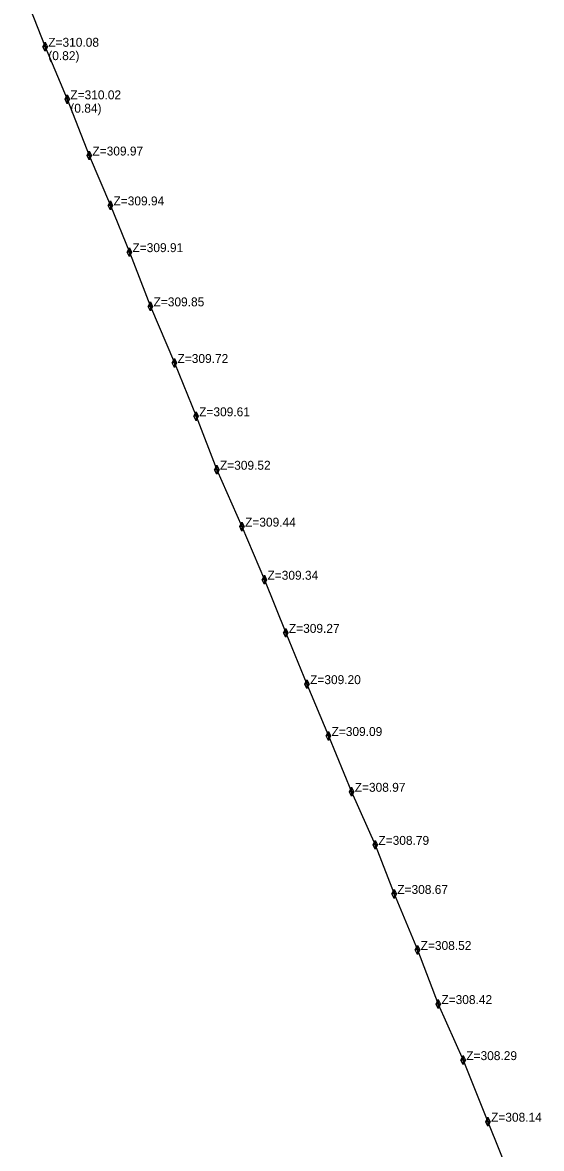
# Model space of a CAD drawing. Extents: x 799271 to 799523, y 67737 to 68184.
# Drawn here: x 799364.5 to 799387.8, y 67960.9 to 68011.4 of the extents above; entities that cross this region are included whole.
import ezdxf

# ---------------------------------------------------------------- set-up
doc = ezdxf.new("R2010")
doc.units = 0
doc.layers.add('PGOC_HTA_CONSTRUIT', color=7, linetype='Continuous')
doc.layers.add('PGOC_PTRL', color=7, linetype='Continuous')

msp = doc.modelspace()

# ---------------------------------------------------------------- linework, layer by layer
at = {"layer": 'PGOC_HTA_CONSTRUIT'}
msp.add_lwpolyline([(799364.509, 68012.954), (799365.523, 68010.352), (799366.514, 68007.996), (799367.503, 68005.475), (799368.447, 68003.238), (799369.299, 68001.141), (799370.244, 67998.71), (799371.319, 67996.17), (799372.29, 67993.779), (799373.221, 67991.381), (799374.349, 67988.83), (799375.353, 67986.448), (799376.313, 67984.066), (799377.264, 67981.766), (799378.226, 67979.44), (799379.265, 67976.938), (799380.327, 67974.558), (799381.173, 67972.357), (799382.222, 67969.845), (799383.151, 67967.417), (799384.268, 67964.903), (799385.38, 67962.141), (799386.421, 67959.533)], dxfattribs=at)
at = {"layer": 'PGOC_PTRL'}
for points in [[(799365.423, 68010.352), (799365.523, 68010.552), (799365.623, 68010.352), (799365.523, 68010.152), (799365.423, 68010.352)], [(799365.623, 68010.352), (799365.523, 68010.352), (799365.423, 68010.352)], [(799365.523, 68010.552), (799365.523, 68010.152)], [(799366.414, 68007.996), (799366.514, 68008.196), (799366.614, 68007.996), (799366.514, 68007.796), (799366.414, 68007.996)], [(799366.614, 68007.996), (799366.514, 68007.996), (799366.414, 68007.996)], [(799366.514, 68008.196), (799366.514, 68007.796)], [(799367.403, 68005.475), (799367.503, 68005.675), (799367.603, 68005.475), (799367.503, 68005.275), (799367.403, 68005.475)], [(799367.603, 68005.475), (799367.503, 68005.475), (799367.403, 68005.475)], [(799367.503, 68005.675), (799367.503, 68005.275)], [(799368.347, 68003.238), (799368.447, 68003.438), (799368.547, 68003.238), (799368.447, 68003.038), (799368.347, 68003.238)], [(799368.447, 68003.438), (799368.447, 68003.038)], [(799368.547, 68003.238), (799368.447, 68003.238), (799368.347, 68003.238)], [(799369.199, 68001.141), (799369.299, 68001.341), (799369.399, 68001.141), (799369.299, 68000.941), (799369.199, 68001.141)], [(799369.299, 68001.341), (799369.299, 68000.941)], [(799369.399, 68001.141), (799369.299, 68001.141), (799369.199, 68001.141)], [(799370.144, 67998.71), (799370.244, 67998.91), (799370.344, 67998.71), (799370.244, 67998.51), (799370.144, 67998.71)], [(799370.244, 67998.91), (799370.244, 67998.51)], [(799370.344, 67998.71), (799370.244, 67998.71), (799370.144, 67998.71)], [(799371.219, 67996.17), (799371.319, 67996.37), (799371.419, 67996.17), (799371.319, 67995.97), (799371.219, 67996.17)], [(799371.319, 67996.37), (799371.319, 67995.97)], [(799371.419, 67996.17), (799371.319, 67996.17), (799371.219, 67996.17)], [(799372.19, 67993.779), (799372.29, 67993.979), (799372.39, 67993.779), (799372.29, 67993.579), (799372.19, 67993.779)], [(799372.39, 67993.779), (799372.29, 67993.779), (799372.19, 67993.779)], [(799372.29, 67993.979), (799372.29, 67993.579)], [(799373.121, 67991.381), (799373.221, 67991.581), (799373.321, 67991.381), (799373.221, 67991.181), (799373.121, 67991.381)], [(799373.321, 67991.381), (799373.221, 67991.381), (799373.121, 67991.381)], [(799373.221, 67991.581), (799373.221, 67991.181)], [(799374.249, 67988.83), (799374.349, 67989.03), (799374.449, 67988.83), (799374.349, 67988.63), (799374.249, 67988.83)], [(799374.449, 67988.83), (799374.349, 67988.83), (799374.249, 67988.83)], [(799374.349, 67989.03), (799374.349, 67988.63)], [(799375.253, 67986.448), (799375.353, 67986.648), (799375.453, 67986.448), (799375.353, 67986.248), (799375.253, 67986.448)], [(799375.353, 67986.648), (799375.353, 67986.248)], [(799375.453, 67986.448), (799375.353, 67986.448), (799375.253, 67986.448)], [(799376.213, 67984.066), (799376.313, 67984.266), (799376.413, 67984.066), (799376.313, 67983.866), (799376.213, 67984.066)], [(799376.313, 67984.266), (799376.313, 67983.866)], [(799376.413, 67984.066), (799376.313, 67984.066), (799376.213, 67984.066)], [(799377.164, 67981.766), (799377.264, 67981.966), (799377.364, 67981.766), (799377.264, 67981.566), (799377.164, 67981.766)], [(799377.364, 67981.766), (799377.264, 67981.766), (799377.164, 67981.766)], [(799377.264, 67981.966), (799377.264, 67981.566)], [(799378.126, 67979.44), (799378.226, 67979.64), (799378.326, 67979.44), (799378.226, 67979.24), (799378.126, 67979.44)], [(799378.226, 67979.64), (799378.226, 67979.24)], [(799378.326, 67979.44), (799378.226, 67979.44), (799378.126, 67979.44)], [(799379.165, 67976.938), (799379.265, 67977.138), (799379.365, 67976.938), (799379.265, 67976.738), (799379.165, 67976.938)], [(799379.265, 67977.138), (799379.265, 67976.738)], [(799379.365, 67976.938), (799379.265, 67976.938), (799379.165, 67976.938)], [(799380.227, 67974.558), (799380.327, 67974.758), (799380.427, 67974.558), (799380.327, 67974.358), (799380.227, 67974.558)], [(799380.427, 67974.558), (799380.327, 67974.558), (799380.227, 67974.558)], [(799380.327, 67974.758), (799380.327, 67974.358)], [(799381.073, 67972.357), (799381.173, 67972.557), (799381.273, 67972.357), (799381.173, 67972.157), (799381.073, 67972.357)], [(799381.173, 67972.557), (799381.173, 67972.157)], [(799381.273, 67972.357), (799381.173, 67972.357), (799381.073, 67972.357)], [(799382.122, 67969.845), (799382.222, 67970.045), (799382.322, 67969.845), (799382.222, 67969.645), (799382.122, 67969.845)], [(799382.222, 67970.045), (799382.222, 67969.645)], [(799382.322, 67969.845), (799382.222, 67969.845), (799382.122, 67969.845)], [(799383.051, 67967.417), (799383.151, 67967.617), (799383.251, 67967.417), (799383.151, 67967.217), (799383.051, 67967.417)], [(799383.151, 67967.617), (799383.151, 67967.217)], [(799383.251, 67967.417), (799383.151, 67967.417), (799383.051, 67967.417)], [(799384.168, 67964.903), (799384.268, 67965.103), (799384.368, 67964.903), (799384.268, 67964.703), (799384.168, 67964.903)], [(799384.368, 67964.903), (799384.268, 67964.903), (799384.168, 67964.903)], [(799384.268, 67965.103), (799384.268, 67964.703)], [(799385.28, 67962.141), (799385.38, 67962.341), (799385.48, 67962.141), (799385.38, 67961.941), (799385.28, 67962.141)], [(799385.48, 67962.141), (799385.38, 67962.141), (799385.28, 67962.141)], [(799385.38, 67962.341), (799385.38, 67961.941)]]:
    msp.add_lwpolyline(points, dxfattribs=at)

# ---------------------------------------------------------------- texts
for s, p in [('Z=310.08', (799365.663, 68010.352)), ('(0.82)', (799365.663, 68009.752)), ('Z=310.02', (799366.654, 68007.996)), ('(0.84)', (799366.654, 68007.396)), ('Z=309.97', (799367.643, 68005.475)), ('Z=309.94', (799368.587, 68003.238)), ('Z=309.91', (799369.439, 68001.141)), ('Z=309.85', (799370.384, 67998.71)), ('Z=309.72', (799371.459, 67996.17)), ('Z=309.61', (799372.43, 67993.779)), ('Z=309.52', (799373.361, 67991.381)), ('Z=309.44', (799374.489, 67988.83)), ('Z=309.34', (799375.493, 67986.448)), ('Z=309.27', (799376.453, 67984.066)), ('Z=309.20', (799377.404, 67981.766)), ('Z=309.09', (799378.366, 67979.44)), ('Z=308.97', (799379.405, 67976.938)), ('Z=308.79', (799380.467, 67974.558)), ('Z=308.67', (799381.313, 67972.357)), ('Z=308.52', (799382.362, 67969.845)), ('Z=308.42', (799383.291, 67967.417)), ('Z=308.29', (799384.408, 67964.903)), ('Z=308.14', (799385.52, 67962.141))]:
    msp.add_text(s, height=0.4, dxfattribs=at).set_placement(p)

doc.saveas('drawing.dxf')
